Omron CX-Programmer project NuevoProyecto (CX-Programmer 9.50)

# PLC NewPLC1: CP1L-E EM

## Program P19_2 (cyclic task 0)
Local symbols
B1 100.00 BOOL
B2 100.01 BOOL
B3 100.02 BOOL
DN1 0.00 BOOL
DN2 0.01 BOOL
DN3 0.02 BOOL
Etapa_0 10.00 BOOL
Etapa_1 10.01 BOOL
Etapa_2 10.02 BOOL
FS_DN1 15.00 BOOL  ; Flanco Subida DN1
FS_DN2 15.01 BOOL  ; Flanco Subida DN2
FS_DN3 15.02 BOOL  ; Flanco Subida DN3

### Section Sección1_Programa_principal
; Etapas X0, X1 y X2

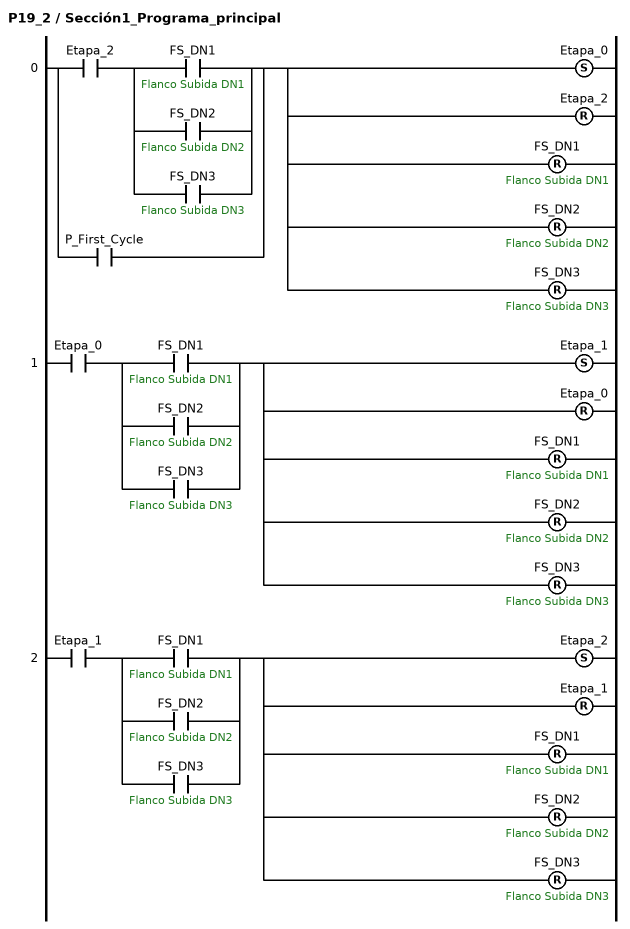
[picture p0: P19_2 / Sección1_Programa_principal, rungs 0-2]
; rung 0
LD Etapa_2
LD FS_DN1  ; Flanco Subida DN1
OR FS_DN2  ; Flanco Subida DN2
OR FS_DN3  ; Flanco Subida DN3
ANDLD
OR P_First_Cycle
SET Etapa_0
RSET Etapa_2
RSET FS_DN1  ; Flanco Subida DN1  // Obligatorio borrar las variables de flanco para que no hayan desplazamientos indeseados entre etapas
RSET FS_DN2  ; Flanco Subida DN2
RSET FS_DN3  ; Flanco Subida DN3
; rung 1
LD Etapa_0
LD FS_DN1  ; Flanco Subida DN1
OR FS_DN2  ; Flanco Subida DN2
OR FS_DN3  ; Flanco Subida DN3
ANDLD
SET Etapa_1
RSET Etapa_0
RSET FS_DN1  ; Flanco Subida DN1
RSET FS_DN2  ; Flanco Subida DN2
RSET FS_DN3  ; Flanco Subida DN3
; rung 2
LD Etapa_1
LD FS_DN1  ; Flanco Subida DN1
OR FS_DN2  ; Flanco Subida DN2
OR FS_DN3  ; Flanco Subida DN3
ANDLD
SET Etapa_2
RSET Etapa_1
RSET FS_DN1  ; Flanco Subida DN1
RSET FS_DN2  ; Flanco Subida DN2
RSET FS_DN3  ; Flanco Subida DN3

### Section Sección2_Flancos

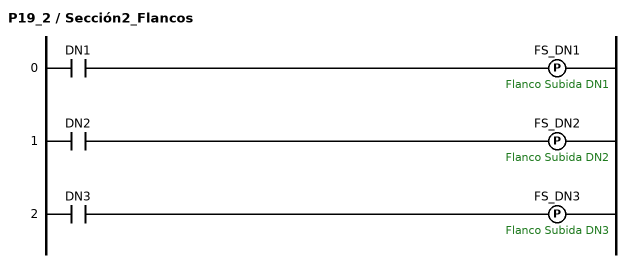
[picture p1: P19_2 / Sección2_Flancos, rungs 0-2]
; rung 0
LD DN1
DIFU(013) FS_DN1  ; Flanco Subida DN1
; rung 1
LD DN2
DIFU(013) FS_DN2  ; Flanco Subida DN2
; rung 2
LD DN3
DIFU(013) FS_DN3  ; Flanco Subida DN3

### Section Sección3_Salidas

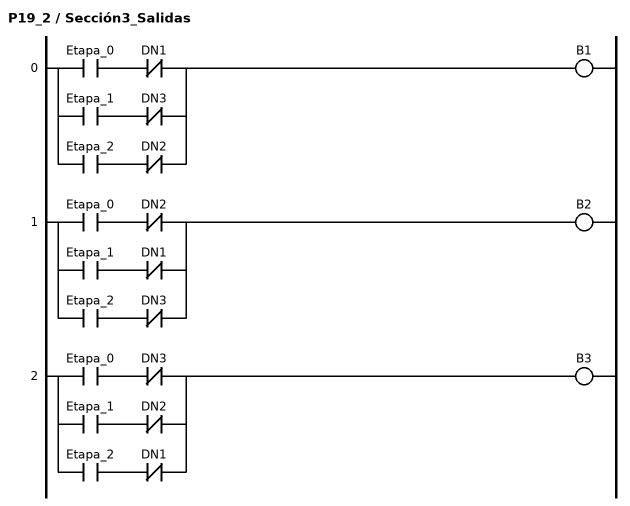
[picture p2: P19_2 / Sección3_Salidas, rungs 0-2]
; rung 0
LD Etapa_0
ANDNOT DN1
LD Etapa_1
ANDNOT DN3
ORLD
LD Etapa_2
ANDNOT DN2
ORLD
OUT B1
; rung 1
LD Etapa_0
ANDNOT DN2
LD Etapa_1
ANDNOT DN1
ORLD
LD Etapa_2
ANDNOT DN3
ORLD
OUT B2
; rung 2
LD Etapa_0
ANDNOT DN3
LD Etapa_1
ANDNOT DN2
ORLD
LD Etapa_2
ANDNOT DN1
ORLD
OUT B3

### Section Sección4_END
; rung 0: Fin de programa
END(001)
